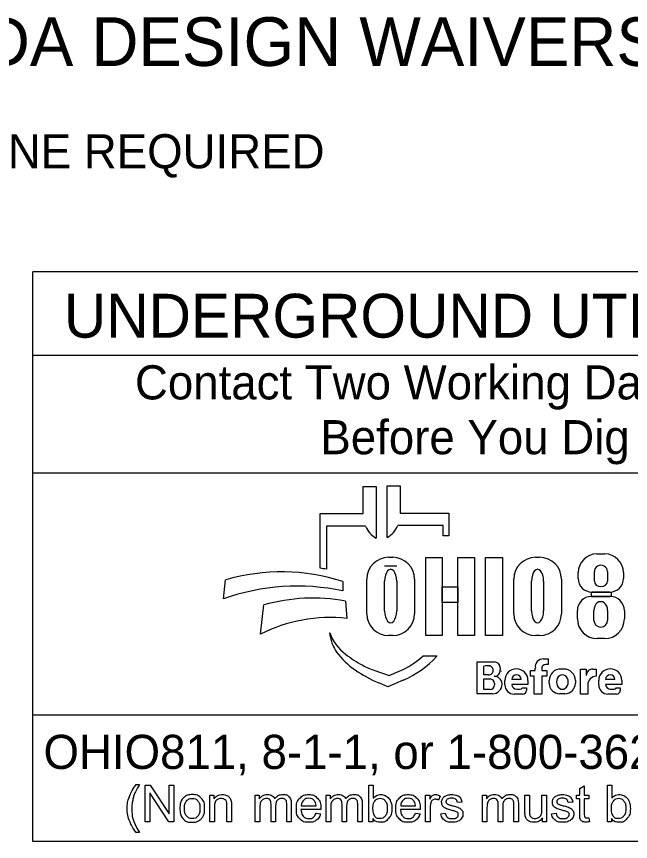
# Model space of a CAD drawing. Extents: x -7.1 to 34, y 0 to 22.
# Drawn here: x 2.311 to 4.831, y 2.143 to 5.529 of the extents above; entities that cross this region are included whole.
import ezdxf

# ---------------------------------------------------------------- set-up
doc = ezdxf.new("R2010")
doc.units = 0
doc.layers.add('SH_Data', color=7, linetype='Continuous')
doc.layers.add('SH_Text', color=7, linetype='Continuous')

msp = doc.modelspace()

# ---------------------------------------------------------------- linework, layer by layer
at = {"layer": 'SH_Data'}
for p, q in [((2.3775, 2.1428), (2.3775, 4.4803)), ((6.6275, 4.4803), (2.3775, 4.4803)), ((2.3775, 4.1387), (6.6275, 4.1387)), ((2.3775, 3.6553), (6.6275, 3.6553)), ((6.6275, 2.6607), (2.3775, 2.6607)), ((6.6275, 2.1428), (2.3775, 2.1428))]:
    msp.add_line(p, q, dxfattribs=at)
at = {"layer": 'SH_Text'}
for p, q in [((3.7335, 3.4883), (3.7335, 3.5998)), ((3.7335, 3.5998), (3.7872, 3.5998)), ((3.7872, 3.5998), (3.7872, 3.3877)), ((3.8329, 3.39), (3.8329, 3.6021)), ((3.8329, 3.6021), (3.8865, 3.6021)), ((3.8865, 3.6021), (3.8865, 3.4906)), ((3.5576, 3.2644), (3.5576, 3.4883)), ((3.5576, 3.4883), (3.7335, 3.4883)), ((3.8865, 3.4906), (4.0857, 3.4906)), ((4.0857, 3.4906), (4.0857, 3.3968)), ((3.5828, 3.4369), (3.5828, 3.26)), ((3.7439, 3.4369), (3.5828, 3.4369)), ((4.0625, 3.4392), (3.8761, 3.4392)), ((4.0625, 3.3968), (4.0625, 3.4392)), ((4.0857, 3.3968), (4.0625, 3.3968)), ((4.6931, 3.3231), (4.7258, 3.3231)), ((3.8385, 3.3091), (3.8551, 3.3091)), ((4.4416, 3.3091), (4.4581, 3.3091)), ((3.8718, 3.2721), (3.822, 3.2721)), ((4.683, 3.2111), (4.683, 3.2504)), ((4.7371, 3.2504), (4.7371, 3.2111)), ((3.7491, 3.0776), (3.7491, 3.2196)), ((3.9445, 3.2196), (3.9445, 3.0776)), ((4.3521, 3.0776), (4.3521, 3.2196)), ((4.5476, 3.2196), (4.5476, 3.0776)), ((4.6168, 3.2225), (4.6168, 3.2468)), ((4.8022, 3.2468), (4.8022, 3.2225)), ((3.1602, 3.1381), (3.1696, 3.2162)), ((3.6509, 3.2097), (3.6509, 3.1709)), ((3.822, 3.089), (3.822, 3.2114)), ((3.8718, 3.2114), (3.8718, 3.089)), ((4.425, 3.089), (4.425, 3.2114)), ((4.4748, 3.2114), (4.4748, 3.089)), ((4.7462, 3.1665), (4.6728, 3.1665)), ((3.6608, 3.1291), (3.6671, 3.0582)), ((4.671, 3.1482), (4.7483, 3.1482)), ((3.312, 2.9936), (3.3267, 3.1137)), ((4.6131, 3.0563), (4.6131, 3.0903)), ((4.6806, 3.0503), (4.6806, 3.0912)), ((4.7374, 3.0912), (4.7374, 3.0503)), ((4.8062, 3.0903), (4.8062, 3.0563)), ((3.5997, 2.9807), (3.5967, 2.9986)), ((3.8551, 2.9882), (3.8385, 2.9882)), ((4.4581, 2.9882), (4.4416, 2.9882)), ((4.7252, 2.9753), (4.6941, 2.9753)), ((3.98, 2.9048), (4.0375, 2.9048)), ((4.2013, 2.749), (4.2013, 2.8798)), ((4.2013, 2.8798), (4.2725, 2.8798)), ((4.4739, 2.8926), (4.4934, 2.8926)), ((4.4934, 2.8926), (4.4934, 2.8696)), ((3.7816, 2.8444), (3.841, 2.8239)), ((4.2293, 2.8263), (4.2293, 2.8632)), ((4.2545, 2.8632), (4.2332, 2.8632)), ((4.2963, 2.856), (4.2963, 2.8481)), ((4.4213, 2.8212), (4.4213, 2.8442)), ((4.4213, 2.8442), (4.4406, 2.8442)), ((4.4406, 2.8442), (4.4406, 2.8546)), ((4.4667, 2.8526), (4.4667, 2.8442)), ((4.4667, 2.8442), (4.4883, 2.8442)), ((4.4934, 2.8691), (4.4832, 2.8691)), ((4.4883, 2.8442), (4.4883, 2.8212)), ((4.5451, 2.8508), (4.5573, 2.8508)), ((4.6254, 2.7478), (4.6254, 2.8505)), ((4.6254, 2.8505), (4.6499, 2.8505)), ((4.6499, 2.8505), (4.6499, 2.8237)), ((4.6772, 2.8505), (4.691, 2.8505)), ((4.691, 2.8505), (4.691, 2.8209)), ((3.841, 2.8239), (3.8821, 2.8417)), ((4.2487, 2.8263), (4.2293, 2.8263)), ((4.4362, 2.8212), (4.4213, 2.8212)), ((4.4362, 2.7478), (4.4362, 2.8212)), ((4.4883, 2.8212), (4.4667, 2.8212)), ((4.4667, 2.8212), (4.4667, 2.7478)), ((3.835, 2.7769), (3.7976, 2.7934)), ((3.8983, 2.8044), (3.835, 2.7769)), ((4.2293, 2.7669), (4.2293, 2.8097)), ((4.2293, 2.8097), (4.2548, 2.8097)), ((4.2729, 2.7916), (4.2729, 2.7853)), ((4.3043, 2.7887), (4.3043, 2.7884)), ((4.3159, 2.7858), (4.3159, 2.8042)), ((4.3824, 2.8082), (4.3439, 2.8082)), ((4.4104, 2.7866), (4.344, 2.7866)), ((4.4104, 2.8042), (4.4104, 2.7866)), ((4.4973, 2.7922), (4.4973, 2.8029)), ((4.6051, 2.8029), (4.6051, 2.7922)), ((4.6559, 2.786), (4.6559, 2.7478)), ((4.7008, 2.7858), (4.7008, 2.8042)), ((4.7674, 2.8082), (4.7288, 2.8082)), ((4.7953, 2.7866), (4.7289, 2.7866)), ((4.7953, 2.8042), (4.7953, 2.7866)), ((4.265, 2.749), (4.2013, 2.749)), ((4.2546, 2.7669), (4.2293, 2.7669)), ((4.3892, 2.7478), (4.3538, 2.7478)), ((4.3649, 2.7673), (4.379, 2.7673)), ((4.3876, 2.7729), (4.4045, 2.7729)), ((4.4045, 2.7729), (4.4045, 2.7631)), ((4.4667, 2.7478), (4.4362, 2.7478)), ((4.5623, 2.7494), (4.5401, 2.7494)), ((4.6559, 2.7478), (4.6254, 2.7478)), ((4.7742, 2.7478), (4.7388, 2.7478)), ((4.7498, 2.7673), (4.7639, 2.7673)), ((4.7725, 2.7729), (4.7894, 2.7729)), ((4.7894, 2.7729), (4.7894, 2.7631))]:
    msp.add_line(p, q, dxfattribs=at)
for points in [[(3.991, 3.3081), (4.0589, 3.3081), (4.0589, 2.9881), (3.991, 2.9881)], [(4.1231, 3.3081), (4.1911, 3.3081), (4.1911, 2.9881), (4.1231, 2.9881)], [(4.2364, 3.3081), (4.3052, 3.3081), (4.3052, 2.9881), (4.2364, 2.9881)], [(4.0589, 3.1882), (4.1231, 3.1882), (4.1231, 3.1242), (4.0589, 3.1242)], [(4.6706, 3.1665), (4.7523, 3.1665), (4.7523, 3.1481), (4.6706, 3.1481)]]:
    msp.add_lwpolyline(points, close=True, dxfattribs=at)
for points in [[(2.8021, 2.3766), (2.8153, 2.3766)], [(2.8389, 2.2239), (2.8389, 2.3741), (2.8592, 2.3741), (2.9382, 2.2561), (2.9382, 2.3741), (2.9572, 2.3741), (2.9572, 2.2239), (2.9369, 2.2239), (2.8579, 2.3419), (2.8579, 2.2239), (2.8389, 2.2239)], [(3.7743, 2.2239), (3.7573, 2.2239), (3.7573, 2.3741), (3.7757, 2.3741), (3.7757, 2.3206)], [(4.6233, 2.2558), (4.6233, 2.3185), (4.6097, 2.3185), (4.6097, 2.3328), (4.6233, 2.3328), (4.6233, 2.3597), (4.6417, 2.3708), (4.6417, 2.3328), (4.6601, 2.3328), (4.6601, 2.3185), (4.6417, 2.3185), (4.6417, 2.2547)], [(4.7534, 2.2239), (4.7363, 2.2239), (4.7363, 2.3741), (4.7548, 2.3741), (4.7548, 2.3206)], [(3.1048, 2.2239), (3.1048, 2.3328), (3.1214, 2.3328), (3.1214, 2.3173)], [(3.2912, 2.2239), (3.2912, 2.3328), (3.3077, 2.3328), (3.3077, 2.3174)], [(3.5826, 2.2239), (3.5826, 2.3328), (3.5991, 2.3328), (3.5991, 2.3174)], [(3.9904, 2.2239), (3.9904, 2.3328), (4.007, 2.3328), (4.007, 2.3163)], [(4.0495, 2.3293), (4.043, 2.3122)], [(4.1394, 2.3046), (4.1213, 2.3022)], [(4.2236, 2.2239), (4.2236, 2.3328), (4.2401, 2.3328), (4.2401, 2.3174)], [(4.3979, 2.2654), (4.3979, 2.3328), (4.4164, 2.3328), (4.4164, 2.2724)], [(4.4676, 2.2745), (4.4676, 2.3328), (4.4861, 2.3328), (4.4861, 2.2239), (4.4696, 2.2239)], [(4.594, 2.3046), (4.5759, 2.3022)], [(3.1233, 2.2833), (3.1233, 2.2239), (3.1048, 2.2239)], [(3.1932, 2.2908), (3.1932, 2.2239), (3.1748, 2.2239), (3.1748, 2.2901)], [(3.3097, 2.2803), (3.3097, 2.2239), (3.2912, 2.2239)], [(3.3743, 2.2871), (3.3743, 2.2239), (3.3559, 2.2239), (3.3559, 2.2946)], [(3.4388, 2.2986), (3.4388, 2.2239), (3.4203, 2.2239), (3.4203, 2.2924)], [(3.56, 2.2736), (3.4788, 2.2736)], [(3.4799, 2.2887), (3.5406, 2.2887)], [(3.601, 2.2803), (3.601, 2.2239), (3.5826, 2.2239)], [(3.6657, 2.2871), (3.6657, 2.2239), (3.6473, 2.2239), (3.6473, 2.2946)], [(3.7301, 2.2986), (3.7301, 2.2239), (3.7117, 2.2239), (3.7117, 2.2924)], [(3.968, 2.2736), (3.8868, 2.2736)], [(3.8879, 2.2887), (3.9486, 2.2887)], [(4.0088, 2.2809), (4.0088, 2.2239), (3.9904, 2.2239)], [(4.242, 2.2803), (4.242, 2.2239), (4.2236, 2.2239)], [(4.3067, 2.2871), (4.3067, 2.2239), (4.2883, 2.2239), (4.2883, 2.2946)], [(4.3711, 2.2986), (4.3711, 2.2239), (4.3527, 2.2239), (4.3527, 2.2924)], [(3.5404, 2.2591), (3.5595, 2.2567)], [(3.7743, 2.2375), (3.7743, 2.2239)], [(3.9484, 2.2591), (3.9675, 2.2567)], [(4.053, 2.2564), (4.0712, 2.2593)], [(4.4696, 2.2239), (4.4696, 2.24)], [(4.5076, 2.2564), (4.5258, 2.2593)], [(4.6601, 2.2404), (4.6628, 2.2241)], [(4.7534, 2.2375), (4.7534, 2.2239)], [(2.8153, 2.1798), (2.8021, 2.1798)]]:
    msp.add_lwpolyline(points, dxfattribs=at)
for centre, radius, start, end in [((3.8353, 3.4736), 0.0985, 201.9296, 240.7469), ((3.7847, 3.476), 0.0985, 299.2531, 338.0704), ((4.6931, 3.2468), 0.0763, 90, 180), ((4.7258, 3.2468), 0.0763, 0, 90), ((3.8385, 3.2196), 0.0895, 90, 180), ((3.8551, 3.2196), 0.0895, 0, 90), ((4.4416, 3.2196), 0.0895, 90, 180), ((4.4581, 3.2196), 0.0895, 0, 90), ((3.4295, 2.4554), 0.8191, 79.2074, 81.0007), ((3.3997, 2.4302), 0.8191, 72.1402, 106.3144), ((4.6728, 3.2225), 0.056, 180, 270), ((4.7462, 3.2225), 0.056, 270, 0), ((3.4628, 2.2991), 0.8919, 77.8238, 109.8274), ((3.5267, 2.4094), 0.7322, 79.44, 105.8467), ((4.671, 3.0903), 0.0579, 90, 180), ((4.7483, 3.0903), 0.0579, 0, 90), ((3.5987, 2.4262), 0.6357, 83.8248, 116.8021), ((3.8385, 3.0776), 0.0895, 180, 270), ((3.8551, 3.0776), 0.0895, 270, 0), ((4.4416, 3.0776), 0.0895, 180, 270), ((4.4581, 3.0776), 0.0895, 270, 0), ((4.6941, 3.0563), 0.081, 180, 270), ((4.7252, 3.0563), 0.081, 270, 0), ((3.7841, 3.0707), 0.2008, 201.0457, 232.5314), ((3.741, 3.0048), 0.1433, 189.6817, 216.0884), ((3.8747, 3.1022), 0.3088, 216.0884, 235.7167), ((3.9766, 3.3219), 0.5173, 232.5314, 241.794), ((3.7387, 3.1722), 0.3602, 293.4582, 312.0712), ((3.7387, 3.1722), 0.401, 293.4582, 317.8286), ((4.2725, 2.856), 0.0238, 0, 90), ((4.4739, 2.859), 0.0335, 90, 187.5187), ((4.0412, 3.3465), 0.6044, 235.7167, 246.2325), ((3.8914, 3.1631), 0.3371, 241.794, 250.9821), ((4.2487, 2.845), 0.0187, 270, 2.0582), ((4.2505, 2.8463), 0.0169, 357.8325, 90), ((4.2721, 2.8453), 0.0243, 270, 6.6529), ((4.3631, 2.8042), 0.0473, 0, 180), ((4.4832, 2.8526), 0.0165, 90, 180), ((4.5451, 2.8029), 0.0478, 90, 180), ((4.5573, 2.8029), 0.0478, 0, 90), ((4.6768, 2.8237), 0.0269, 89.2449, 180), ((4.7481, 2.8042), 0.0473, 0, 180), ((4.2722, 2.7889), 0.0321, 4.0748, 90), ((4.2827, 2.8438), 0.0175, 347.4023, 0), ((4.3632, 2.8072), 0.0193, 2.9632, 177.0368), ((4.6908, 2.786), 0.0349, 89.6033, 180), ((4.7481, 2.8072), 0.0193, 2.9632, 177.0368), ((4.2546, 2.7853), 0.0184, 270, 0), ((4.2548, 2.7916), 0.0181, 0, 90), ((4.265, 2.7884), 0.0393, 270, 0), ((4.2714, 2.7887), 0.033, 0, 11.7502), ((4.3538, 2.7858), 0.038, 180, 270), ((4.3649, 2.7883), 0.021, 184.827, 270), ((4.5401, 2.7922), 0.0428, 180, 270), ((4.5623, 2.7922), 0.0428, 270, 0), ((4.7388, 2.7858), 0.038, 180, 270), ((4.7498, 2.7883), 0.021, 184.827, 270), ((4.379, 2.7767), 0.00938, 270, 335.9979), ((4.3892, 2.7631), 0.0152, 270, 0), ((4.7639, 2.7767), 0.00938, 270, 335.9979), ((4.7742, 2.7631), 0.0152, 270, 0)]:
    msp.add_arc(centre, radius, start, end, dxfattribs=at)
for centre, major_axis, ratio, start_param, end_param in [((3.8469, 3.2114), (0, 0.0484), 0.514403, 4.712389, 7.853982), ((4.4499, 3.2114), (0, 0.0484), 0.514403, 4.712389, 7.853982), ((4.71, 3.2504), (0.0271, 0), 0.969373, 0, 3.141593), ((4.71, 3.2111), (0.0271, 0), 0.818453, 3.141593, 6.283185), ((4.709, 3.0912), (0, 0.0358), 0.794529, 4.712389, 7.853982), ((3.8469, 3.089), (0, 0.0484), 0.514403, 1.570796, 4.712389), ((4.4499, 3.089), (0, 0.0484), 0.514403, 1.570796, 4.712389), ((4.709, 3.0503), (0.0284, 0), 0.959837, 3.141593, 6.283185), ((4.5517, 2.7976), (0, 0.029), 0.832186, 4.712389, 7.853982), ((4.5517, 2.7976), (0, 0.0302), 0.797287, 1.570796, 4.712389)]:
    msp.add_ellipse(centre, major_axis=major_axis, ratio=ratio, start_param=start_param, end_param=end_param, dxfattribs=at)
for points in [[(2.8021, 2.1798), (2.7869, 2.199), (2.7763, 2.2248), (2.7657, 2.2506), (2.7657, 2.2783), (2.7657, 2.3026), (2.7736, 2.325), (2.7829, 2.3509), (2.8021, 2.3766)], [(2.8153, 2.3766), (2.8029, 2.3553), (2.7989, 2.3462), (2.7927, 2.332), (2.7891, 2.3167), (2.7847, 2.2975), (2.7847, 2.2782), (2.7847, 2.2289), (2.8153, 2.1798)], [(2.9814, 2.2783), (2.9814, 2.3085), (2.9981, 2.3231), (3.0122, 2.3352), (3.0323, 2.3352), (3.0547, 2.3352), (3.069, 2.3205), (3.0832, 2.3058), (3.0832, 2.2799), (3.0832, 2.2589), (3.0769, 2.2469), (3.0706, 2.2348), (3.0586, 2.2282), (3.0466, 2.2215), (3.0323, 2.2215), (3.0095, 2.2215), (2.9954, 2.2362), (2.9814, 2.2508), (2.9814, 2.2783)], [(3.0003, 2.2783), (3.0003, 2.2574), (3.0094, 2.247), (3.0185, 2.2366), (3.0323, 2.2366), (3.046, 2.2366), (3.0551, 2.2471), (3.0642, 2.2575), (3.0642, 2.279), (3.0642, 2.2991), (3.0551, 2.3095), (3.0459, 2.3199), (3.0323, 2.3199), (3.0185, 2.3199), (3.0094, 2.3096), (3.0003, 2.2992), (3.0003, 2.2783)], [(3.1214, 2.3173), (3.1334, 2.3352), (3.156, 2.3352), (3.1659, 2.3352), (3.1741, 2.3316), (3.1823, 2.3281), (3.1864, 2.3224), (3.1905, 2.3166), (3.1922, 2.3087), (3.1932, 2.3036), (3.1932, 2.2908)], [(3.1748, 2.2901), (3.1748, 2.3013), (3.1726, 2.3069), (3.1705, 2.3125), (3.165, 2.3158), (3.1595, 2.3191), (3.1521, 2.3191), (3.1404, 2.3191), (3.1318, 2.3117), (3.1233, 2.3042), (3.1233, 2.2833)], [(3.3077, 2.3174), (3.3128, 2.3254), (3.3214, 2.3303), (3.3299, 2.3352), (3.3407, 2.3352), (3.3528, 2.3352), (3.3606, 2.3301), (3.3683, 2.3251), (3.3715, 2.3161), (3.3844, 2.3352), (3.4051, 2.3352), (3.4213, 2.3352), (3.43, 2.3262), (3.4388, 2.3172), (3.4388, 2.2986)], [(3.3559, 2.2946), (3.3559, 2.3069), (3.3514, 2.313), (3.3469, 2.3191), (3.3366, 2.3191), (3.3288, 2.3191), (3.3222, 2.315), (3.3156, 2.311), (3.3126, 2.3031), (3.3097, 2.2952), (3.3097, 2.2803)], [(3.4203, 2.2924), (3.4203, 2.3035), (3.4185, 2.3083), (3.4168, 2.3132), (3.412, 2.3162), (3.4073, 2.3191), (3.401, 2.3191), (3.3895, 2.3191), (3.3819, 2.3115), (3.3743, 2.3039), (3.3743, 2.2871)], [(3.5595, 2.2567), (3.555, 2.24), (3.5428, 2.2307), (3.5306, 2.2215), (3.5117, 2.2215), (3.4878, 2.2215), (3.4738, 2.2362), (3.4598, 2.2509), (3.4598, 2.2774), (3.4598, 2.3049), (3.474, 2.32), (3.4881, 2.3352), (3.5106, 2.3352), (3.5324, 2.3352), (3.5463, 2.3203), (3.5601, 2.3055), (3.5601, 2.2785), (3.5601, 2.2769), (3.56, 2.2736)], [(3.5406, 2.2887), (3.5394, 2.3025), (3.5337, 2.3094), (3.5249, 2.3201), (3.5108, 2.3201), (3.4981, 2.3201), (3.4894, 2.3115), (3.4808, 2.303), (3.4799, 2.2887)], [(3.5991, 2.3174), (3.6042, 2.3254), (3.6127, 2.3303), (3.6212, 2.3352), (3.6321, 2.3352), (3.6442, 2.3352), (3.6519, 2.3301), (3.6597, 2.3251), (3.6628, 2.3161), (3.6758, 2.3352), (3.6965, 2.3352), (3.7127, 2.3352), (3.7214, 2.3262), (3.7301, 2.3172), (3.7301, 2.2986)], [(3.6473, 2.2946), (3.6473, 2.3069), (3.6428, 2.313), (3.6383, 2.3191), (3.628, 2.3191), (3.6202, 2.3191), (3.6136, 2.315), (3.607, 2.311), (3.604, 2.3031), (3.601, 2.2952), (3.601, 2.2803)], [(3.7117, 2.2924), (3.7117, 2.3035), (3.7099, 2.3083), (3.7081, 2.3132), (3.7034, 2.3162), (3.6987, 2.3191), (3.6923, 2.3191), (3.6809, 2.3191), (3.6733, 2.3115), (3.6657, 2.3039), (3.6657, 2.2871)], [(3.7741, 2.2792), (3.7741, 2.2596), (3.7794, 2.2509), (3.7881, 2.2366), (3.8029, 2.2366), (3.815, 2.2366), (3.8238, 2.2471), (3.8326, 2.2576), (3.8326, 2.2784), (3.8326, 2.2998), (3.8241, 2.3099), (3.8157, 2.3201), (3.8038, 2.3201), (3.7917, 2.3201), (3.7829, 2.3096), (3.7741, 2.299), (3.7741, 2.2792)], [(3.7757, 2.3206), (3.7874, 2.3352), (3.8055, 2.3352), (3.8155, 2.3352), (3.8245, 2.3311), (3.8335, 2.3271), (3.8392, 2.3198), (3.845, 2.3124), (3.8483, 2.3021), (3.8516, 2.2918), (3.8516, 2.28), (3.8516, 2.252), (3.8378, 2.2368), (3.8239, 2.2215), (3.8046, 2.2215), (3.7853, 2.2215), (3.7743, 2.2375)], [(3.9675, 2.2567), (3.963, 2.24), (3.9508, 2.2307), (3.9386, 2.2215), (3.9196, 2.2215), (3.8958, 2.2215), (3.8818, 2.2362), (3.8678, 2.2509), (3.8678, 2.2774), (3.8678, 2.3049), (3.882, 2.32), (3.8961, 2.3352), (3.9186, 2.3352), (3.9404, 2.3352), (3.9543, 2.3203), (3.9681, 2.3055), (3.9681, 2.2785), (3.9681, 2.2769), (3.968, 2.2736)], [(3.9486, 2.2887), (3.9474, 2.3025), (3.9417, 2.3094), (3.9328, 2.3201), (3.9188, 2.3201), (3.9061, 2.3201), (3.8974, 2.3115), (3.8888, 2.303), (3.8879, 2.2887)], [(4.007, 2.3163), (4.0133, 2.3278), (4.0187, 2.3315), (4.0241, 2.3352), (4.0305, 2.3352), (4.0398, 2.3352), (4.0495, 2.3293)], [(4.043, 2.3122), (4.0363, 2.3162), (4.0295, 2.3162), (4.0235, 2.3162), (4.0187, 2.3125), (4.0139, 2.3089), (4.0119, 2.3024), (4.0088, 2.2926), (4.0088, 2.2809)], [(4.1213, 2.3022), (4.1201, 2.3106), (4.1142, 2.3153), (4.1083, 2.3201), (4.0975, 2.3201), (4.0848, 2.3201), (4.0794, 2.3159), (4.0739, 2.3116), (4.0739, 2.306), (4.0739, 2.3024), (4.0762, 2.2995), (4.0785, 2.2966), (4.0833, 2.2946), (4.086, 2.2936), (4.0996, 2.2899), (4.1192, 2.2847), (4.1269, 2.2813), (4.1347, 2.278), (4.1391, 2.2717), (4.1435, 2.2653), (4.1435, 2.2559), (4.1435, 2.2467), (4.1381, 2.2386), (4.1327, 2.2304), (4.1226, 2.226), (4.1124, 2.2215), (4.0996, 2.2215), (4.0784, 2.2215), (4.0672, 2.2303), (4.0561, 2.2391), (4.053, 2.2564)], [(4.0712, 2.2593), (4.0727, 2.2483), (4.0798, 2.2425), (4.0868, 2.2366), (4.0995, 2.2366), (4.1122, 2.2366), (4.1184, 2.2418), (4.1245, 2.247), (4.1245, 2.254), (4.1245, 2.2602), (4.1191, 2.2638), (4.1153, 2.2663), (4.1002, 2.2701), (4.0799, 2.2752), (4.072, 2.2789), (4.0642, 2.2827), (4.0601, 2.2893), (4.0561, 2.2959), (4.0561, 2.3038), (4.0561, 2.3111), (4.0594, 2.3173), (4.0628, 2.3235), (4.0685, 2.3276), (4.0728, 2.3308), (4.0803, 2.333), (4.0877, 2.3352), (4.0962, 2.3352), (4.109, 2.3352), (4.1187, 2.3315), (4.1284, 2.3278), (4.133, 2.3215), (4.1377, 2.3152), (4.1394, 2.3046)], [(4.2401, 2.3174), (4.2452, 2.3254), (4.2537, 2.3303), (4.2622, 2.3352), (4.2731, 2.3352), (4.2852, 2.3352), (4.2929, 2.3301), (4.3007, 2.3251), (4.3038, 2.3161), (4.3168, 2.3352), (4.3375, 2.3352), (4.3537, 2.3352), (4.3624, 2.3262), (4.3711, 2.3172), (4.3711, 2.2986)], [(4.2883, 2.2946), (4.2883, 2.3069), (4.2838, 2.313), (4.2793, 2.3191), (4.269, 2.3191), (4.2612, 2.3191), (4.2546, 2.315), (4.248, 2.311), (4.245, 2.3031), (4.242, 2.2952), (4.242, 2.2803)], [(4.3527, 2.2924), (4.3527, 2.3035), (4.3509, 2.3083), (4.3491, 2.3132), (4.3444, 2.3162), (4.3397, 2.3191), (4.3333, 2.3191), (4.3219, 2.3191), (4.3143, 2.3115), (4.3067, 2.3039), (4.3067, 2.2871)], [(4.5759, 2.3022), (4.5747, 2.3106), (4.5688, 2.3153), (4.5629, 2.3201), (4.5521, 2.3201), (4.5394, 2.3201), (4.5339, 2.3159), (4.5285, 2.3116), (4.5285, 2.306), (4.5285, 2.3024), (4.5308, 2.2995), (4.533, 2.2966), (4.5378, 2.2946), (4.5406, 2.2936), (4.5542, 2.2899), (4.5737, 2.2847), (4.5815, 2.2813), (4.5893, 2.278), (4.5937, 2.2717), (4.5981, 2.2653), (4.5981, 2.2559), (4.5981, 2.2467), (4.5927, 2.2386), (4.5873, 2.2304), (4.5772, 2.226), (4.567, 2.2215), (4.5542, 2.2215), (4.5329, 2.2215), (4.5218, 2.2303), (4.5107, 2.2391), (4.5076, 2.2564)], [(4.5258, 2.2593), (4.5273, 2.2483), (4.5343, 2.2425), (4.5414, 2.2366), (4.554, 2.2366), (4.5668, 2.2366), (4.5729, 2.2418), (4.5791, 2.247), (4.5791, 2.254), (4.5791, 2.2602), (4.5736, 2.2638), (4.5698, 2.2663), (4.5548, 2.2701), (4.5345, 2.2752), (4.5266, 2.2789), (4.5188, 2.2827), (4.5147, 2.2893), (4.5107, 2.2959), (4.5107, 2.3038), (4.5107, 2.3111), (4.514, 2.3173), (4.5173, 2.3235), (4.5231, 2.3276), (4.5274, 2.3308), (4.5348, 2.333), (4.5423, 2.3352), (4.5508, 2.3352), (4.5636, 2.3352), (4.5733, 2.3315), (4.583, 2.3278), (4.5876, 2.3215), (4.5922, 2.3152), (4.594, 2.3046)], [(4.7532, 2.2792), (4.7532, 2.2596), (4.7585, 2.2509), (4.7672, 2.2366), (4.782, 2.2366), (4.7941, 2.2366), (4.8029, 2.2471), (4.8116, 2.2576), (4.8116, 2.2784), (4.8116, 2.2998), (4.8032, 2.3099), (4.7948, 2.3201), (4.7828, 2.3201), (4.7708, 2.3201), (4.762, 2.3096), (4.7532, 2.299), (4.7532, 2.2792)], [(4.7548, 2.3206), (4.7664, 2.3352), (4.7846, 2.3352), (4.7946, 2.3352), (4.8036, 2.3311), (4.8125, 2.3271), (4.8183, 2.3198), (4.8241, 2.3124), (4.8274, 2.3021), (4.8306, 2.2918), (4.8306, 2.28), (4.8306, 2.252), (4.8168, 2.2368), (4.803, 2.2215), (4.7836, 2.2215), (4.7644, 2.2215), (4.7534, 2.2375)], [(3.4788, 2.2736), (3.4799, 2.2557), (3.489, 2.2462), (3.4981, 2.2366), (3.5117, 2.2366), (3.5219, 2.2366), (3.5291, 2.242), (3.5362, 2.2473), (3.5404, 2.2591)], [(3.8868, 2.2736), (3.8879, 2.2557), (3.897, 2.2462), (3.9061, 2.2366), (3.9197, 2.2366), (3.9299, 2.2366), (3.937, 2.242), (3.9442, 2.2473), (3.9484, 2.2591)], [(4.4164, 2.2724), (4.4164, 2.258), (4.4175, 2.253), (4.4192, 2.2457), (4.4249, 2.2416), (4.4305, 2.2374), (4.4388, 2.2374), (4.4471, 2.2374), (4.4543, 2.2417), (4.4616, 2.2459), (4.4646, 2.2533), (4.4676, 2.2606), (4.4676, 2.2745)], [(4.4696, 2.24), (4.4569, 2.2215), (4.4351, 2.2215), (4.4255, 2.2215), (4.4171, 2.2252), (4.4088, 2.2289), (4.4047, 2.2345), (4.4007, 2.2401), (4.3991, 2.2482), (4.3979, 2.2536), (4.3979, 2.2654)], [(4.6628, 2.2241), (4.655, 2.2224), (4.6488, 2.2224), (4.6388, 2.2224), (4.6333, 2.2256), (4.6278, 2.2288), (4.6255, 2.234), (4.6233, 2.2392), (4.6233, 2.2558)], [(4.6417, 2.2547), (4.6417, 2.2468), (4.6427, 2.2445), (4.6436, 2.2423), (4.6458, 2.2409), (4.648, 2.2396), (4.6521, 2.2396), (4.6551, 2.2396), (4.6601, 2.2404)]]:
    msp.add_open_spline(points, degree=3, dxfattribs=at)

# ---------------------------------------------------------------- texts
for s, height, p in [('ADA DESIGN WAIVERS', 0.2, (1.9944, 5.3256)), ('NONE REQUIRED', 0.14, (1.9944, 4.9056)), ('UNDERGROUND UTILITIES', 0.18, (2.5057, 4.2106)), ('Contact Two Working Days', 0.14, (2.7972, 3.9571)), ('Before You Dig', 0.14, (3.5583, 3.7321)), ('OHIO811, 8-1-1, or 1-800-362-2764', 0.14, (2.422, 2.4406))]:
    msp.add_text(s, height=height, dxfattribs=at).set_placement(p)

doc.saveas('drawing.dxf')
